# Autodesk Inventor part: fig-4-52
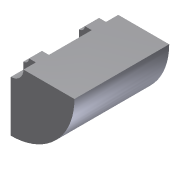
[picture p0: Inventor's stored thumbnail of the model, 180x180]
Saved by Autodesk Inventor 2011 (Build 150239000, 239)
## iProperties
Created: 2010-02
Part Number: fig-4-52
Document SubType Name: Modeling
Designer: CADSoft
Density: 1 g/cm^3
Author: CADSoft
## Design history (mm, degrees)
sketch "Sketch1"
  geometry: L1 (4.005, 30.039)-(20.155, 30.039); L2 (20.155, 30.039)-(20.155, 0); L3 (20.155, 0)-(4.005, 0); L4 (4.005, 26.163)-(1.809, 26.163); L5 (1.809, 26.163)-(1.809, 21.641); L6 (1.809, 21.641)-(4.005, 21.641); L7 (4.005, 3.941)-(1.809, 3.941); L8 (1.809, 3.941)-(1.809, 8.075); L9 (1.809, 8.075)-(4.005, 8.075); L10 (4.005, 26.163)-(4.005, 30.039); L11 (4.005, 0)-(4.005, 3.941); L12 (4.005, 8.075)-(4.005, 21.641); L13 (0, 31.977)-(0, -5.62); 1 further point
  constraints: 26 end point
revolve "Revolution1" sketch "Sketch1" stored, may be unused: angle "d0" = 90 deg
body "Solid1"
